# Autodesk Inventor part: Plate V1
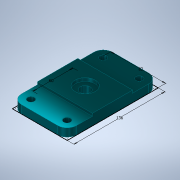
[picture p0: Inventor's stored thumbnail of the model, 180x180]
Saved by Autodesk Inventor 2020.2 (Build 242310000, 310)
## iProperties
Created: 2018-06
Part Number: Plate V1
Material: Aluminum 6061
Document SubType Name: Modeling
Designer: Power User
Density: 2.7 g/cm^3
Appearance: Steel - Polished(2)
Mass: 384.04 g
Surface Area: 295.629 cm^2
Volume: 142.237 cm^3
Author: Power User
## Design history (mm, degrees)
sketch "Sketch1"
  geometry: L1 (41, 68)-(-41, 68); L2 (-41, 68)-(-41, -68); L3 (-41, -68)-(41, -68); L4 (41, -68)-(41, 68); L5 (41, 68)-(-41, -68); L6 (-41, 68)-(41, -68); L7 (-41, -30)-(41, -30); L8 (41, -30)-(41, 30); L9 (41, 30)-(-41, 30); L10 (-41, 30)-(-41, -30); L11 (-41, -30)-(41, 30); L12 (41, -30)-(-41, 30); 1 further point
  constraints: 24 end point, 4 midpoint, 4 parallel, 2 horizontal, 2 perpendicular, 1 collinear
  dimensions: "d0" = 82 distance of L3.end L2.end; "d1" = 136 distance of L2.end L1.end; "d3" = 60 distance between parallel lines of L7 L9
extrude "Extrusion1" new body sketch "Sketch1" distance "d4" = 12; taper "d5" = 0 deg
extrude "Extrusion2" join sketch "Sketch1" distance "d6" = 16; taper "d7" = 0 deg
fillet "Fillet1" dims "d8" = 14
sketch "Sketch3"
  geometry: A1 r 14 centre (-27, -54) between (-41, -54) and (-27, -68) reference; A2 r 14 centre (-27, 54) between (-27, 68) and (-41, 54) reference; A3 r 14 centre (27, 54) between (41, 54) and (27, 68) reference; A4 r 14 centre (27, -54) between (27, -68) and (41, -54) reference; 5 further points
  constraints: 4 coincident
hole "Hole2" sketch "Sketch3" at (-27, -54), (-27, 54), (27, 54), (27, -54) diameter "d16" = 10; stored, may be unused: countersink angle "d20" = 90 deg, drill point angle "d22" = 118 deg; dims "d17" = 6, "d18" = 4, "d19" = 2, "d21" = 8
sketch "Sketch6"
  geometry: L1 (-41, -30)-(41, -30) reference; L2 (41, -30)-(41, 30) reference; 2 further points
  dimensions: "d51" = 30 distance from line of L1 point (0, 0) (= 0.5 x d3); "d52" = 41 distance from line of L2 point (0, 0) (= 0.5 x d0)
hole "Hole5" sketch "Sketch6" at (0, 0) diameter "d53" = 15; stored, may be unused: countersink angle "d57" = 90 deg, drill point angle "d59" = 118 deg; dims "d54" = 6, "d55" = 30, "d56" = 5, "d58" = 8
body "Solid1"
sketch "Sketch4"
  geometry: 1 further point
